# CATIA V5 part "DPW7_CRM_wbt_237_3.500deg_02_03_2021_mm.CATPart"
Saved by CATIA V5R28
Part number: DPW7_CRM_wbt_237_3.500deg_02_03_2021
Bounding box of the stored display mesh (mm): x 2349.5 to 66711.891, y 0 to 29545.854, z 2310.119 to 8715.756
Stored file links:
  Z:\Scratch\04_CAD_Allgemein\Flight2Jig\Output\DPW-7\CATPart\DPW7_CRM_wbt_182_3.500deg_02_03_2021.CATPart
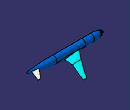
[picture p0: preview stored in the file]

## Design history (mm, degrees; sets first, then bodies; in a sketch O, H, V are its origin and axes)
Set1
  DatumSurface1 "Clean_Wing"
  DatumSurface2 "Fuselage"
  DatumSurface3 "HTP"
  DatumSurface4 "Symmetry"
  DatumSurface5 "Farfield"
Body1 (main body)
